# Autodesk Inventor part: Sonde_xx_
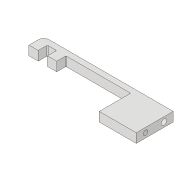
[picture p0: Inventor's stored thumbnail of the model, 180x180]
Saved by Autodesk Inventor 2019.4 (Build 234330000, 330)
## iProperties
Created: 2018-06
Part Number: Sonde_xx_
Material: ABS-Kunststoff
Document SubType Name: Modeling
Designer: Alfred
Mass: 3.0672 g
Surface Area: 23.2501 cm^2
Volume: 2.89358 cm^3
Density: 1.06 g/cm^3
Appearance: Glatt - weiß
Author: Alfred
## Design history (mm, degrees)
sketch "Skizze1"
  geometry: L1 (-35, -10)-(-35, -30); L2 (-55, -30)-(-55, -13); L3 (-55, -13)-(-90, -13); L4 (-90, -13)-(-90, -18); L5 (-90, -18)-(-95, -18); L6 (-95, -18)-(-95, -13); L7 (-95, -13)-(-100, -13); L8 (-100, -13)-(-100, -18); L9 (-100, -18)-(-105, -18); L10 (-105, -18)-(-105, -10); L11 (-55, -30)-(-35, -30); L12 (-105, -10)-(-35, -10)
  constraints: 24 end point, 8 perpendicular, 4 point on line, 3 equal length, 1 vertical
  dimensions: "d4" = 20 distance of L2.start L1.end; "d1" = 70 distance of L1.start L10.end; "d2" = 5 distance of L8.end L9.end; "d3" = 5 distance of L3.end L4.end; "d0" = 3 distance between parallel lines of L3 L12
extrude "Extrusion1" new body sketch "Skizze1" taper "d6" = 0 deg; stored distance "d7" = 5
fillet "Rundungskerbe" dims "d8" = 0.5
sketch "Bohrungsskizze"
  geometry: L1 (5, 20)-(0, 20) reference; L2 (0, 0)-(0, 20) reference; L3 (0, 0)-(5, 0) reference; L4 (5, 20)-(5, 0) reference; L5 (0, 10)-(5, 10); L6 (2.5, 0)-(2.5, 20); 2 further points
  constraints: 4 end point, 3 midpoint, 2 point on line, 1 perpendicular, 1 symmetric about line
  dimensions: "d9" = 10 distance of point (2.5, 15) point (2.5, 5)
hole "Stiftbohrung" sketch "Bohrungsskizze" diameter "d10" = 3; stored, may be unused: countersink angle "d14" = 90 deg, drill point angle "d16" = 118 deg; dims "d11" = 6, "d12" = 4, "d13" = 2, "d15" = 8
hole "Gewindebohrung" sketch "Bohrungsskizze" diameter "d17" = 2.459; stored, may be unused: countersink angle "d21" = 90 deg, drill point angle "d23" = 118 deg; dims "d18" = 6, "d19" = 4, "d20" = 2, "d22" = 8
fillet "Rundung2" dims "d24" = 3
fillet "Rundung3" dims "d25" = 0.5
node "Volumenkörper1"
